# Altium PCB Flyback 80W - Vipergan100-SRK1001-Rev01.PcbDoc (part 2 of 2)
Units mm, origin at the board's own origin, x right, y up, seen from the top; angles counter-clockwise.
Board outline 121.92 x 39.12 mm, 2 copper layers (Top Layer, Bottom Layer), stack 1.58 mm thick; 100 components, 56 nets, 249 pads, 157 vias.
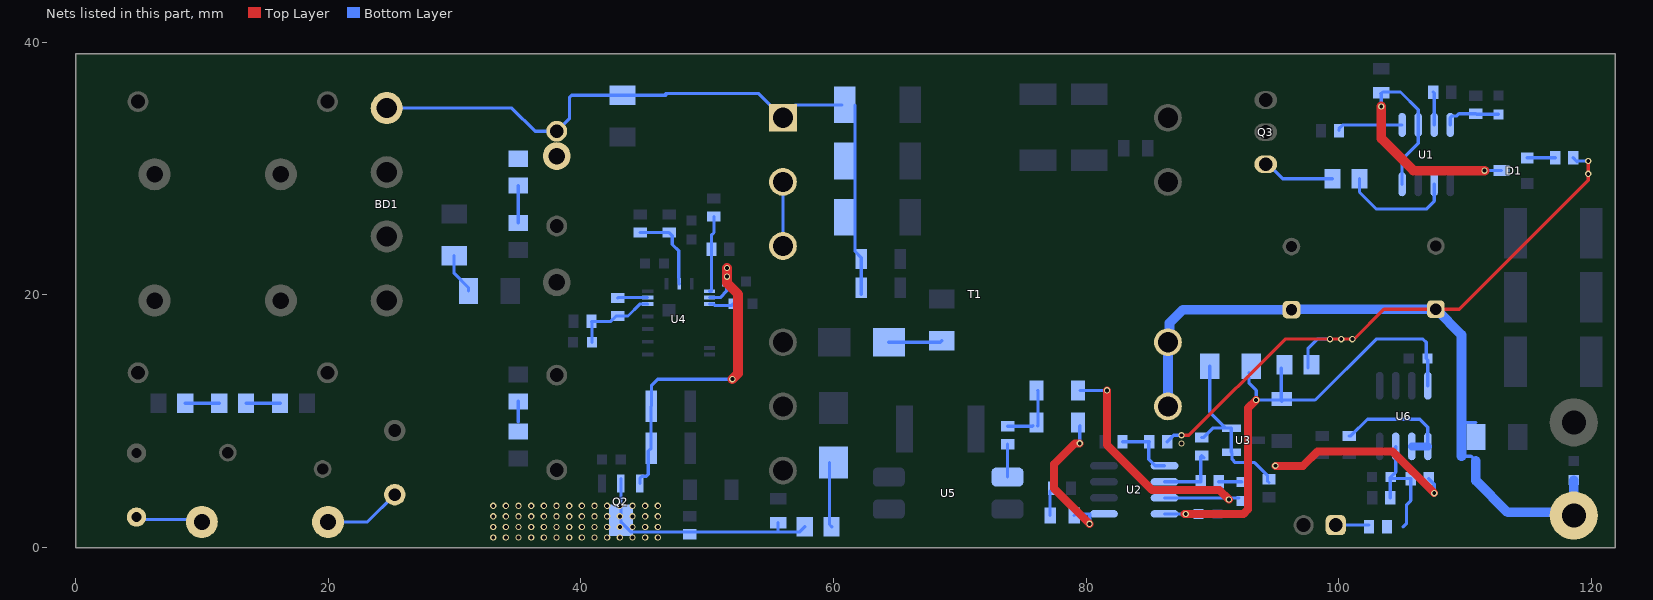
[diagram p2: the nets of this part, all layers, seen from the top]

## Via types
v1: diameter 0.508, hole 0.305, Top Layer to Bottom Layer, 157 vias

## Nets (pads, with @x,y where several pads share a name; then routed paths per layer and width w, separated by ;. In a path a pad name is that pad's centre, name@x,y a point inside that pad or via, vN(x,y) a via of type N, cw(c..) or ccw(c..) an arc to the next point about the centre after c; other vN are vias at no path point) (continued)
NetC12_2: C12.2 Q2.C R20.1 R24.2 | length 18.8
  Bottom Layer w0.254: Q2.C@43.18,2.18 43.18,2.052 44.003,1.229 55.626,1.229 ; Q2.C@43.18,2.561 Q2.C@43.18,5.461 ; C12.2@55.626,1.971 55.626,1.229 ; R20.1@57.734,1.651 57.312,1.229 55.626,1.229
  other v1: 35.073,0.8 36.075,0.8 37.078,0.8 38.08,0.8 39.083,0.8 40.085,0.8 41.088,0.8 42.091,0.8 43.093,0.8 44.096,0.8 45.098,0.8 46.101,0.8 33.067,0.801 34.07,0.801 33.067,1.634 34.07,1.634 35.073,1.633 36.075,1.633 37.078,1.633 38.08,1.633 39.083,1.633 40.085,1.633 41.088,1.633 42.091,1.633 43.093,1.633 44.096,1.633 45.098,1.633 46.101,1.633 33.067,2.468 34.07,2.468 35.073,2.467 36.075,2.467 37.078,2.467 38.08,2.467 39.083,2.467 40.085,2.467 41.088,2.467 42.091,2.467 43.093,2.467 44.096,2.467 45.098,2.467 46.101,2.467 33.067,3.303 34.07,3.303 35.073,3.302 36.075,3.302 37.078,3.302 38.08,3.302 39.083,3.302 40.085,3.302 41.088,3.3 42.091,3.3 43.093,3.3 44.096,3.3 45.098,3.3 46.101,3.3
NetC13_2: C13.2 R25.1 U1.8 | length 4.5
  Bottom Layer w0.254: U1.8@108.839,33.465 108.839,34.021 108.999,34.181 109.365,34.181 109.525,34.341 R25.1@110.871,34.341 110.91,34.302 C13.2@112.649,34.302
NetC19_1: C19.1 R30.1 | length 2.3
  Bottom Layer w0.254: C19.1@77.155,2.54 77.155,4.46 R30.1@77.394,4.699
NetC19_2: C19.2 D6.A U2.1 | length 12.1
  Top Layer w0.635: v1(79.502,8.255) 79.121,8.255 77.47,6.604 77.47,4.691 v1(80.28,1.882)
  Bottom Layer w0.254: C19.2@79.055,2.54 79.182,2.667 80.301,2.667 80.301,1.903 v1(80.28,1.882) ; v1(79.502,8.255) 79.502,9.628 D6.A@79.526,9.652
NetC20_2: C20.2 U4.13 | length 2
  Bottom Layer w0.254: U4.13@50.19,19.296 50.49,19.296 50.609,19.177 51.955,19.177 C20.2@52.082,19.304
NetC23_2: C23.2 R36.1 R40.2 U4.5 | length 6.7
  Bottom Layer w0.254: C23.2@40.882,16.256 40.882,17.868 R40.2@40.843,17.907 42.367,17.907 42.799,18.339 R36.1@42.926,18.339 43.739,18.339 44.678,19.278 45.272,19.278 U4.5@45.29,19.296
NetC24_1: C24.1 D7.A U2.7 | length 23.8
  Top Layer w0.635: v1(81.661,12.446) 81.661,8.128 85.217,4.572 90.551,4.572 v1(91.313,3.81)
  Bottom Layer w0.254: D7.A@79.526,12.446 v1(81.661,12.446) ; U2.7@86.22,3.937 C24.1@92.087,3.937
NetC24_2: C24.2 R35.1 | length 1.8
  Bottom Layer w0.254: R35.1@90.5,5.207 92.317,5.207 C24.2@92.329,5.195
NetC27_2: C27.2 R29.2 R46.2 R47.1 U6.3 | length 10
  Bottom Layer w0.254: R29.2@104.089,3.937 104.089,5.549 C27.2@104.128,5.588 ; U6.3@104.521,8.014 104.521,5.981 C27.2@104.128,5.588 ; 105.105,1.651 105.385,1.93 105.385,3.391 105.715,3.721 R46.2@105.715,5.461 104.255,5.461 C27.2@104.128,5.588
NetD1_A: D1.A R19.2 | length 2.2
  Bottom Layer w0.254: D1.A@114.935,30.861 R19.2@117.145,30.861
NetD3_K: D3.K R17.2 | length 4.2
  Bottom Layer w0.254: D3.K@64.389,16.256 68.453,16.256 R17.2@68.58,16.383
NetD5_K: D5.K R20.2 | length 5.2
  Bottom Layer w0.254: D5.K@59.69,6.731 59.69,1.829 R20.2@59.868,1.651
NetD6_K: D6.K D7.K R42.2 | length 4.8
  Bottom Layer w0.254: R42.2@73.787,9.601 75.744,9.601 D6.K@75.795,9.652 ; D6.K@76.176,9.652 76.2,9.676 76.2,12.422 D7.K@76.176,12.446
NetF1_1: F1.1 N.1 | length 5.3
  Bottom Layer w0.254: F1.1@4.826,2.413 5.016,2.222 9.81,2.222 N.1@10,2.032
NetL_1: L.1 NTC1.1 | length 6.2
  Bottom Layer w0.254: L.1@20,2.032 23.114,2.032 NTC1.1@25.273,4.191
NetP1_1: P1.1 R47.2 | length 2.6
  Bottom Layer w0.254: P1.1@99.77,1.778 R47.2@102.413,1.778
NetQ3_G: Q3.G R26.1 | length 5.8
  Bottom Layer w0.254: Q3.G@94.234,30.353 94.434,30.353 95.577,29.21 R26.1@99.517,29.21
NetR1_2: R1.2 R2.1 | length 2.7
  Bottom Layer w0.254: R2.1@13.513,11.43 R1.2@16.205,11.43
NetR2_2: R2.2 R7.1 | length 2.7
  Bottom Layer w0.254: R7.1@8.687,11.43 R2.2@11.379,11.43
NetR3_2: R3.2 R4.2 | length 2.9
  Bottom Layer w0.254: R4.2@35.052,25.705 R3.2@35.052,28.651
NetR5_2: R5.2 R6.1 | length 3.3
  Bottom Layer w0.254: R5.2@29.972,23.114 29.972,21.717 31.115,20.574 R6.1@31.115,20.32
NetR8_2: R8.2 R9.1 | length 1.6
  Bottom Layer w0.254: 35.052,9.957 R8.2@35.052,11.582
NetR18_2: R18.2 U1.5 | length 5.3
  Bottom Layer w0.254: R18.2@100.025,33.02 100.025,33.147 100.343,33.465 U1.5@105.029,33.465
NetR21_1: R21.1 U1.7 | length 2.6
  Bottom Layer w0.254: R21.1@107.493,36.068 107.569,35.992 U1.7@107.569,33.465
NetR26_2: R26.2 U1.2 | length 9.1
  Bottom Layer w0.254: R26.2@101.651,29.21 101.651,28.143 102.997,26.797 106.934,26.797 107.569,27.432 U1.2@107.569,28.765
NetR35_2: R35.2 R41.1 U2.6 | length 5.2
  Bottom Layer w0.254: U2.6@86.22,5.207 R35.2@89.078,5.207 89.078,7.214 R41.1@89.154,7.29 R41.1@89.332,7.112
NetR36_2: R36.2 U4.6 | length 2.4
  Bottom Layer w0.254: R36.2@42.926,19.761 42.961,19.796 U4.6@45.29,19.796
NetR39_2: R39.2 R43.1 U2.5 | length 5
  Bottom Layer w0.254: R43.1@82.88,8.382 R39.2@85.014,8.382 84.963,8.331 84.963,6.983 85.469,6.477 U2.5@86.22,6.477
NetR42_1: R42.1 U5.1 | length 2.6
  Bottom Layer w0.254: U5.1@73.787,5.588 R42.1@73.787,8.179
NetR48_2: R48.2 U6.1 U6.2 | length 9.8
  Bottom Layer w0.254: R48.2@100.838,8.839 100.965,8.839 102.286,10.16 106.426,10.16 107.061,9.525 U6.1@107.061,8.014
  Bottom Layer w0.635: U6.2@105.791,8.014 U6.1@107.061,8.014
NetT1_2: T1.2 T1.3 | length 5.1
  Bottom Layer w0.254: T1.3@56.007,23.876 T1.2@56.007,28.956
TB: R37.2 R44.1 U4.9 | length 6.7
  Bottom Layer w0.254: R37.2@44.704,24.943 R44.1@46.99,24.943 47.248,24.685 47.248,23.999 47.752,23.495 47.752,21.354 47.767,21.339 47.767,20.919 U4.9@47.79,20.896
Vcc_SRK: C14.2 D1.K U1.4 U1.6 | length 24
  Top Layer w0.762: v1(103.378,34.925) 103.378,32.385 105.918,29.845 v1(111.55,29.845)
  Bottom Layer w0.254: v1(103.378,34.925) 103.378,35.875 103.312,35.941 103.378,35.941 103.505,36.068 104.902,36.068 106.299,34.671 106.299,32.004 105.029,30.734 U1.4@105.029,28.765 ; v1@111.76,29.845 D1.K@112.903,29.845
Vdc_Bus: BD1.1 C3.2 C9.2 C10.2 pad.2@38.1,31 R3.1 R11.1 R12.1 R13.1 R22.1 T1.1 | length 55.4
  Bottom Layer w0.254: BD1.1@24.638,34.798 34.544,34.798 36.382,32.96 C3.2@38.1,32.96 39.116,33.976 39.116,35.665 39.265,35.814 46.736,35.814 ; 46.736,35.941 54.102,35.941 T1.1@56.007,34.036 57.023,35.052 R13.1@60.693,35.052 ; R13.1@61.709,35.052 61.709,30.607 61.709,26.162 61.709,23.451 62.204,22.956 62.204,22.606 C9.2@62.204,20.066
Vdd_Viper: C17.2 C18.2 C21.2 Q2.E U4.12 | length 27.3
  Top Layer w0.762: v1(51.574,22.135) 51.574,20.943 52.451,20.066 52.451,13.781 v1(52.005,13.335)
  Bottom Layer w0.254: Q2.E@44.68,5.08 44.68,5.48 44.853,5.653 45.19,5.653 45.339,5.802 45.339,7.646 C17.2@45.567,7.874 C18.2@45.567,11.176 45.593,11.202 45.593,12.827 46.101,13.335 v1(52.005,13.335) ; U4.12@50.19,19.796 51.038,19.796 51.562,20.32 51.562,21.07 C21.2@51.574,21.082 v1(51.574,21.457) ; 51.574,21.832 v1(51.574,22.135)
Vout: C6.1 C7.1 C8.2 R19.1 R23.1 R33.1 R39.1 T1.8 T1.9 V+.1 | length 104.7
  Top Layer w0.254: v1@87.503,8.89 v1(87.561,8.89) 88.138,8.89 95.758,16.51 v1(99.314,16.51) v1(100.203,16.51) v1(101.092,16.51) 101.219,16.51 103.585,18.876 C7.1@107.696,18.876 109.554,18.876 119.761,29.083 v1(119.761,29.591) v1(119.761,30.607)
  Bottom Layer w0.254: R39.1@86.436,8.382 86.944,8.89 v1@87.503,8.89 ; R33.1@97.587,14.224 97.587,15.799 98.298,16.51 v1(99.314,16.51) ; 109.728,7.239 110.49,7.239 110.871,6.858 ; 109.728,9.906 110.871,9.906 ; R19.1@118.567,30.861 118.872,30.556 118.923,30.607 v1(119.761,30.607)
  Bottom Layer w0.762: T1.8@86.487,11.176 T1.9@86.487,16.256 86.614,16.383 86.614,17.78 87.67,18.836 C6.1@96.266,18.836 96.286,18.856 107.676,18.856 C7.1@107.696,18.876 109.728,16.844 109.728,9.906 109.728,7.239 ; 110.871,6.858 110.871,5.299 113.376,2.794 118.364,2.794 V+.1@118.618,2.54 C8.2@118.618,5.346
  other v1: 87.561,8.243
Vref: R32.2 R34.2 R41.2 R46.1 U3.1 U3.2 | length 30.2
  Top Layer w0.635: v1(94.996,6.477) 97.189,6.477 98.332,7.62 104.267,7.62 v1(107.569,4.318)
  Bottom Layer w0.254: R41.2@89.154,8.712 89.281,8.712 90.028,9.459 U3.2@91.056,9.459 ; R32.2@89.789,14.351 89.789,10.726 U3.2@91.056,9.459 ; R34.2@94.488,5.156 94.361,5.283 94.361,5.715 93.345,6.731 91.821,6.731 91.567,6.985 91.567,7.498 U3.1@91.506,7.559 U3.2@91.506,9.459 U3.2@91.056,9.459 ; R46.1@107.137,5.461 107.569,5.029 v1(107.569,4.318)
Vreg: C25.2 C28.2 DZ3.K R32.1 R33.2 U2.8 U6.8 | length 40.9
  Top Layer w0.635: v1@87.8,2.661 92.465,2.661 92.837,3.033 92.837,11.049 v1(93.472,11.684)
  Bottom Layer w0.254: U2.8@86.22,2.667 C25.2@88.912,2.667 ; R32.1@92.913,13.843 92.913,13.005 93.472,12.446 v1(93.472,11.684) 95.401,11.684 DZ3.K@95.453,11.632 ; R33.2@95.453,14.224 DZ3.K@95.453,11.632 ; U6.8@107.061,12.814 107.061,14.847 106.922,14.986 106.934,14.998 106.934,16.256 106.68,16.51 102.966,16.51 98.14,11.684 95.607,11.684 95.504,11.581 DZ3.K@95.453,11.632
  other v1: 87.9,2.661
ZCD: R38.2 R45.1 U4.11 | length 6.1
  Bottom Layer w0.254: U4.11@50.19,20.296 50.32,20.296 50.343,20.319 50.343,22.606 50.343,24.74 50.546,24.943 R38.2@50.546,26.213
pads on no net: D1.NC U6.5 U6.6 U6.7

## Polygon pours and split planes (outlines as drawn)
GND-Out on Bottom Layer "NONET_L02_P-001" (solid, pour order 234): 97.663,0.381 98.298,1.016 98.298,2.604 98.869,3.175 105.054,3.175 106.162,4.298 106.162,8.372 106.162,15.855 90.922,15.855 88.392,13.325 88.392,9.525 87.239,8.372 84.308,8.372 83.312,9.368 83.312,16.002 82.55,16.764 78.613,16.764 77.079,15.23 77.079,9.886 75.428,8.235 75.428,7.473 75.428,7.346 75.428,5.822 75.306,5.7 73.782,5.7 72.136,4.054 72.136,3.038 72.136,1.143 72.898,0.381
GND-prim on Bottom Layer "NONET_L02_P-001" (solid, pour order 192): 53.911,18.287 53.658,18.034 49.631,18.034 48.26,16.663 48.26,14.859 46.228,14.859 39.751,8.382 39.751,6.096 38.735,5.08 31.369,5.08 28.194,8.255 28.194,13.335 23.622,17.907 23.114,17.907 22.733,18.288 22.733,20.701 23.114,21.082 25.527,21.082 26.416,20.193 26.416,18.669 30.734,14.351 30.734,9.271 32.258,7.747 37.084,7.747 37.084,7.239 37.465,7.239 37.465,9.398 44.704,16.637 44.704,18.288 44.958,18.542 47.616,18.542 47.871,18.288
NetC12_2 on Bottom Layer "NONET_L02_P-001" (solid, pour order 290): 32.258,3.556 32.639,3.937 39.751,3.937 40.005,3.683 42.291,3.683 42.672,4.064 42.672,5.969 43.561,5.969 43.561,4.318 44.069,3.81 46.482,3.81 46.863,3.429 46.863,1.905 47.244,1.524 50.292,1.524 51.689,2.921 58.293,2.921 58.547,2.667 58.547,0.635 58.293,0.381 32.639,0.381 32.258,0.762
NetC5_2 on Bottom Layer "NONET_L02_P-001" (solid, pour order 289): 49.53,1.905 47.752,1.905 47.498,2.159 47.498,3.683 46.736,4.445 46.736,5.461 46.863,5.588 49.403,5.588 49.657,5.334 49.657,2.032
GND-prim on Bottom Layer "NONET_L02_P-001" (solid, pour order 240): 38.1,16.024 37.915,16.209 37.915,18.865 38.1,19.05 38.862,19.05 43.376,23.564 43.376,31.242 51.689,31.242 52.959,29.972 52.959,22.733 54.229,21.463 54.229,18.605 53.658,18.034 45.667,18.034 42.238,14.605 39.497,14.605 39.001,15.101 38.1,16.002
NetC9_1 on Bottom Layer "NONET_L02_P-001" (solid, pour order 183): 69.596,37.719 69.596,24.384 70.104,23.876 70.104,19.304 69.723,18.923 65.151,18.923 64.516,19.558 64.516,23.876 64.897,24.257 64.897,37.719 65.405,38.227 69.088,38.227
Drain_Viper on Bottom Layer "NONET_L02_P-001" (solid, pour order 170): 56.896,14.986 57.531,14.351 61.087,14.351 61.468,14.732 61.468,17.78 55.626,17.78 53.848,16.002 49.53,16.002 49.53,14.986
NetD5_K on Bottom Layer "NONET_L02_P-001" (solid, pour order 272): 58.42,8.382 61.595,8.382 61.849,8.128 61.849,0.635 61.595,0.381 59.182,0.381 59.055,0.508 59.055,3.302 58.166,4.191 58.166,8.128
NetC2_1 on Bottom Layer "NONET_L02_P-001" (solid, pour order 288): 22.352,9.398 21.717,9.398 20.447,8.128 19.812,7.493 18.796,7.493 18.542,7.239 18.542,5.461 18.796,5.207 21.844,5.207 24.511,7.874 25.908,7.874 26.416,8.382 26.416,11.43 23.241,14.605 22.352,14.605 20.193,16.764 20.193,18.034 17.018,21.209 15.113,21.209 14.478,20.574 14.478,18.415 17.653,15.24 17.653,10.033 17.907,9.779 22.352,9.779
NetC2_2 on Bottom Layer "NONET_L02_P-001" (solid, pour order 287): 12.573,6.35 13.081,6.858 13.081,8.89 12.573,9.398 8.001,9.398 7.239,10.16 7.239,17.907 7.874,18.542 7.874,20.828 7.366,21.336 4.445,21.336 3.556,20.447 3.556,6.858 4.064,6.35
NetF1_1 on Bottom Layer "NONET_L02_P-001" (solid, pour order 285): 3.683,0.381 3.302,0.762 3.302,3.175 3.683,3.556 11.176,3.556 11.557,3.175 11.557,0.762 11.176,0.381
NetL_1 on Bottom Layer "NONET_L02_P-001" (solid, pour order 284): 24.257,0.381 26.416,2.54 26.416,4.826 25.908,5.334 24.511,5.334 22.987,3.81 18.923,3.81 18.415,3.302 18.415,0.889 18.923,0.381
GND-Sec on Bottom Layer "NONET_L02_P-001" (solid, pour order 283): 74.168,34.671 74.549,34.29 81.28,34.29 83.439,36.449 88.392,36.449 89.154,35.687 90.043,36.576 91.821,36.576 91.821,38.1 91.313,38.608 74.549,38.608 74.168,38.227
NetC11_1 on Bottom Layer "NONET_L02_P-001" (solid, pour order 282): 83.566,27.813 82.931,27.178 74.676,27.178 74.168,27.686 74.168,32.131 81.28,32.131 82.042,32.893 83.312,32.893 83.566,32.639
Drain_SR on Bottom Layer "NONET_L02_P-001" (solid, pour order 281): 87.249,27.051 87.884,27.686 87.884,35.179 87.503,35.56 84.836,35.56 84.455,35.179 84.455,27.559 84.963,27.051
HV on Bottom Layer "NONET_L02_P-001" (solid, pour order 279): 42.037,33.528 44.831,33.528 44.958,33.401 44.958,31.623 43.18,29.845 43.18,24.257 43.561,23.876 46.355,23.876 47.117,23.114 47.112,20.313 47.092,20.294 46.488,20.294 46.488,21.711 46.045,22.154 46.045,23.075 45.625,23.495 43.053,23.495 41.402,25.146 41.402,32.893
NetC5_2 on Bottom Layer "NONET_L02_P-001" (solid, pour order 278): 42.037,4.064 42.164,4.191 42.164,8.382 42.037,8.509 41.148,8.509 41.021,8.382 41.021,4.191 41.148,4.064
GND-prim on Bottom Layer "NONET_L02_P-001" (solid, pour order 277): 42.545,6.35 43.942,6.35 44.069,6.477 44.069,10.033 43.942,10.16 42.545,10.16 42.418,10.033 42.418,6.477
Vdd_Viper on Bottom Layer "NONET_L02_P-001" (solid, pour order 276): 49.276,13.843 52.324,13.843 52.451,13.716 52.451,13.081 52.324,12.954 49.281,12.959 47.118,12.955 46.228,12.065 46.228,4.826 45.72,4.318 44.323,4.318 44.323,12.192 45.974,13.843
GND-prim on Bottom Layer "NONET_L02_P-001" (solid, pour order 275): 63.881,12.319 63.817,12.255 63.627,12.065 63.627,7.874 64.516,6.985 66.294,6.985 66.294,4.064 66.167,3.937 62.992,3.937 62.865,3.81 62.865,0.635 63.119,0.381 65.786,0.381 67.056,1.651 67.056,11.811 66.548,12.319
GND-prim on Bottom Layer "NONET_L02_P-001" (solid, pour order 271): 48.006,5.969 50.546,5.969 51.308,5.207 51.308,3.429 56.642,3.429 57.277,4.064 57.277,6.731 56.642,7.366 52.324,7.366 51.689,8.001 51.689,12.065 51.054,12.7 48.133,12.7 47.625,12.192 47.625,6.35
Vout on Bottom Layer "NONET_L02_P-001" (solid, pour order 229): 108.458,6.223 108.458,4.953 113.03,0.381 114.3,0.381 120.523,0.381 121.539,1.397 121.539,4.699 120.396,5.842 117.729,5.842 116.586,4.699 113.792,4.699 111.76,6.731 111.76,10.668 111.506,10.922 111.506,18.542 109.22,20.828 87.503,20.828 84.836,18.161 84.836,10.668 85.725,9.779 87.503,9.779 88.011,10.287 88.011,16.129 89.535,17.653 107.442,17.653 108.077,17.018 108.077,6.604
Vout on Bottom Layer "NONET_L02_P-001" (solid, pour order 270): 118.364,32.004 118.11,31.75 118.11,29.337 118.364,29.083 120.142,29.083 120.396,29.337 120.396,31.75 120.142,32.004
NetC27_2 on Bottom Layer "NONET_L02_P-001" (solid, pour order 269): 103.637,3.17 103.632,3.164 103.632,2.794 103.378,2.54 103.378,0.635 103.632,0.381 106.045,0.381 106.489,0.825 106.489,3.874 106.172,4.191 106.172,6.223 106.045,6.35 105.283,6.35 105.029,6.604 105.029,9.144 104.902,9.271 104.267,9.271 104.14,9.144 104.14,6.731 103.632,6.223 103.632,3.175
NetP1_1 on Bottom Layer "NONET_L02_P-001" (solid, pour order 268): 102.87,2.921 103.124,2.667 103.124,0.635 102.87,0.381 99.06,0.381 98.806,0.635 98.806,2.667 99.06,2.921
GND-Sec on Bottom Layer "NONET_L02_P-001" (solid, pour order 265): 115.189,33.017 112.9,30.734 110.998,30.734 110.744,30.48 110.744,27.559 110.617,27.432 106.172,27.432 105.918,27.686 105.918,30.607 107.315,32.004 109.22,32.004 110.363,33.147 113.538,33.147 113.792,33.401 113.792,35.179 113.665,35.306 108.458,35.306 108.331,35.433 108.331,37.465 108.204,37.592 106.299,37.592 105.918,37.211 99.06,37.211 96.52,34.671 93.599,34.671 93.599,38.1 94.107,38.608 113.665,38.608 115.189,37.084
NetR21_1 on Bottom Layer "NONET_L02_P-001" (solid, pour order 264): 107.823,32.385 107.95,32.512 107.95,37.211 107.823,37.338 106.553,37.338 106.426,37.211 106.426,35.433 107.188,34.671 107.188,32.512 107.315,32.385
NetC13_2 on Bottom Layer "NONET_L02_P-001" (solid, pour order 263): 109.22,32.385 110.236,33.401 113.411,33.401 113.538,33.528 113.538,34.798 113.411,34.925 108.839,34.925 108.458,34.544 108.458,32.512 108.585,32.385
NetR26_2 on Bottom Layer "NONET_L02_P-001" (solid, pour order 262): 101.219,30.607 100.965,30.353 100.965,27.178 101.6,26.543 107.569,26.543 107.95,26.924 107.95,29.591 107.823,29.718 107.315,29.718 107.188,29.591 107.188,27.559 106.807,27.178 104.013,27.178 103.124,28.067 103.124,30.226 102.743,30.607
Vcc_SRK on Bottom Layer "NONET_L02_P-001" (solid, pour order 261): 102.362,36.576 104.775,36.576 106.68,34.671 106.68,32.004 105.41,30.734 105.41,27.686 105.283,27.559 104.775,27.559 104.648,27.686 104.648,30.861 105.918,32.131 105.918,34.544 105.41,35.052 104.267,35.052 103.759,34.544 102.362,34.544 102.108,34.798 102.108,36.322
NetR18_2 on Bottom Layer "NONET_L02_P-001" (solid, pour order 260): 104.648,34.544 104.267,34.163 99.695,34.163 99.568,34.036 99.568,32.004 99.695,31.877 104.775,31.877 105.41,32.512 105.41,34.417 105.283,34.544
Drain_SR on Bottom Layer "NONET_L02_P-001" (solid, pour order 259): 96.901,33.655 97.409,34.163 98.933,34.163 99.06,34.036 99.06,32.004 98.933,31.877 97.282,31.877 97.028,32.131 93.345,32.131 93.218,32.258 93.218,33.528 93.345,33.655
Vcc_SRK on Bottom Layer "NONET_L02_P-001" (solid, pour order 258): 113.538,30.48 111.506,30.48 111.252,30.226 111.252,29.337 111.506,29.083 113.538,29.083 113.665,29.21 113.665,30.353
NetD1_A on Bottom Layer "NONET_L02_P-001" (solid, pour order 256): 114.808,32.131 117.348,32.131 117.602,31.877 117.602,29.337 117.348,29.083 116.586,29.083 115.443,30.226 114.427,30.226 114.3,30.353 114.3,31.623
Vref on Bottom Layer "NONET_L02_P-001" (solid, pour order 255): 106.807,6.35 107.95,6.35 108.077,6.223 108.077,4.191 107.823,3.937 106.934,3.937 106.68,4.191 106.68,6.223
NetR48_2 on Bottom Layer "NONET_L02_P-001" (solid, pour order 251): 100.203,8.382 101.727,8.382 101.854,8.509 101.854,9.144 102.489,9.779 104.902,9.779 105.41,9.271 105.41,6.985 105.664,6.731 107.315,6.731 107.569,6.985 107.569,9.906 106.934,10.541 100.203,10.541 100.076,10.414 100.076,8.509
NetR35_2 on Bottom Layer "NONET_L02_P-001" (solid, pour order 131): 88.011,5.588 88.265,5.842 88.265,7.62 88.392,7.747 89.789,7.747 89.916,7.62 89.916,6.604 89.535,6.223 89.535,4.445 88.138,4.445 87.757,4.826 85.09,4.826 84.963,4.953 84.963,5.461 85.09,5.588
Vref on Bottom Layer "NONET_L02_P-001" (solid, pour order 250): 90.551,15.875 90.678,15.748 90.678,10.922 91.44,10.16 92.202,10.16 92.329,10.033 92.329,9.144 92.202,9.017 92.202,8.128 92.329,8.001 92.329,7.239 93.091,7.239 93.472,6.858 95.377,6.858 95.631,6.604 95.631,5.207 95.377,4.953 93.599,4.953 93.345,5.207 93.345,5.969 93.091,6.223 90.805,6.223 90.297,6.731 90.297,7.874 89.916,8.255 88.392,8.255 88.138,8.509 88.138,9.652 88.392,9.906 88.392,15.748 88.519,15.875
GND-Sec on Bottom Layer "NONET_L02_P-001" (solid, pour order 244): 70.104,6.858 70.104,11.811 83.312,25.019 88.519,25.019 89.408,25.908 90.424,24.892 90.551,24.892 90.551,24.765 92.964,22.352 82.677,22.352 72.009,11.684 72.009,6.858
NetR5_2 on Bottom Layer "NONET_L02_P-001" (solid, pour order 249): 28.575,24.003 28.575,19.558 29.337,18.796 31.75,18.796 32.131,19.177 32.131,21.971 31.496,22.606 31.496,24.003
NetBD1_3 on Bottom Layer "NONET_L02_P-001" (solid, pour order 248): 31.369,27.813 28.194,27.813 26.416,26.035 21.336,26.035 20.828,25.527 5.207,25.527 3.556,27.178 3.556,33.909 3.937,33.909 3.937,28.067 4.318,27.686 7.493,27.686 8.001,28.194 8.001,36.195 7.366,36.83 2.286,36.83 0.762,35.306 0.762,26.162 3.81,23.114 25.908,23.114 28.321,25.527 31.369,25.527
NetBD1_2 on Bottom Layer "NONET_L02_P-001" (solid, pour order 247): 21.463,31.369 21.082,31.75 21.082,36.195 20.32,36.957 15.748,36.957 14.351,35.56 14.351,28.956 15.621,27.686 17.526,27.686 18.669,28.829 18.669,33.909 19.05,33.909 19.05,29.337 20.193,28.194 25.527,28.194 26.162,28.829 26.162,30.734 25.527,31.369
Vout on Bottom Layer "NONET_L02_P-001" (solid, pour order 245): 98.425,13.081 101.473,16.129 101.473,16.891 101.346,17.018 97.536,17.018 97.155,16.637 97.155,13.081
GND-Sec on Bottom Layer "NONET_L02_P-001" (solid, pour order 233): 97.663,8.382 99.568,8.382 99.568,9.525 99.822,9.779 99.822,10.414 99.695,10.541 98.044,10.541 97.663,10.16
In- on Bottom Layer "NONET_L02_P-001" (solid, pour order 230): 97.663,7.874 101.727,7.874 101.727,6.35 101.092,5.715 98.425,5.715 97.663,6.477
GND-Out on Bottom Layer "NONET_L02_P-001" (solid, pour order 226): 113.157,10.541 113.411,10.795 116.586,10.795 118.237,12.446 118.237,27.432 118.618,27.813 121.158,27.813 121.539,27.432 121.539,7.493 120.523,6.477 116.586,6.477 116.332,6.731 116.332,7.874 116.078,7.874 116.078,6.731 115.824,6.477 113.411,6.477 113.157,6.731
GND-Sec on Bottom Layer "NONET_L02_P-001" (solid, pour order 225): 115.443,11.684 115.189,11.43 112.268,11.43 112.014,11.684 112.014,20.32 109.982,22.352 91.821,22.352 89.154,25.019 89.154,37.211 90.551,38.608 94.361,38.608 95.504,37.465 95.504,35.052 95.123,34.671 92.329,34.671 91.694,34.036 91.694,26.543 92.71,25.527 110.109,25.527 112.268,27.686 114.808,27.686 115.443,27.051
NetQ3_G on Bottom Layer "NONET_L02_P-001" (solid, pour order 222): 100.203,28.067 99.949,27.813 94.488,27.813 92.837,29.464 92.837,30.734 93.345,31.242 94.996,31.242 95.631,30.607 99.949,30.607 100.203,30.353
Vreg on Bottom Layer "NONET_L02_P-001" (solid, pour order 216): 96.266,10.922 96.774,11.43 98.298,11.43 103.124,16.256 106.045,16.256 106.553,15.748 106.553,14.478 106.68,14.351 106.68,11.557 106.807,11.43 107.569,11.43 107.696,11.557 107.696,16.51 107.315,16.891 102.743,16.891 98.171,12.319 97.028,12.319 96.52,12.827 96.52,15.494 96.139,15.875 94.488,15.875 94.361,15.748 94.361,12.192 94.107,12.192 94.107,15.748 93.98,15.875 92.329,15.875 92.202,15.748 92.202,11.684 92.964,10.922
NetR8_2 on Bottom Layer "NONET_L02_P-001" (solid, pour order 191): 36.322,11.938 36.322,8.89 35.941,8.509 33.909,8.509 33.528,8.89 33.528,11.938 33.909,12.319 35.941,12.319
NetC23_2 on Bottom Layer "NONET_L02_P-001" (solid, pour order 206): 42.291,15.748 44.069,17.526 44.069,18.288 44.831,19.05 45.72,19.05 45.72,19.431 44.323,19.431 43.688,18.796 40.64,18.796 40.386,18.542 40.386,15.748
Aux on Bottom Layer "NONET_L02_P-001" (solid, pour order 205): 43.688,25.781 43.688,28.194 44.704,29.21 50.673,29.21 51.308,28.575 51.308,27.178 49.784,27.178 48.641,28.321 46.609,28.321 45.72,27.432 45.72,25.781
NetC20_2 on Bottom Layer "NONET_L02_P-001" (solid, pour order 204): 49.67,19.469 49.67,18.669 52.54,18.669 52.54,19.748 52.514,19.774 52.489,19.748 51.727,19.748 51.448,19.469
Vdd_Viper on Bottom Layer "NONET_L02_P-001" (solid, pour order 203): 49.708,19.634 49.708,19.964 50.775,19.964 51.079,20.269 51.079,21.514 50.927,21.666 50.927,22.301 51.079,22.454 51.994,22.454 52.172,22.276 52.172,21.539 51.968,21.336 51.968,20.371 51.232,19.634
ZCD on Bottom Layer "NONET_L02_P-001" (solid, pour order 202): 49.53,20.117 50.648,20.117 50.724,20.193 50.724,20.574 50.597,20.701 50.597,22.885 50.775,23.063 50.775,24.613 51.562,25.4 51.562,26.645 49.962,26.645 49.53,26.213
FB on Bottom Layer "NONET_L02_P-001" (solid, pour order 200): 48.26,24.892 48.26,23.876 48.387,23.749 48.387,20.574 48.514,20.447 49.149,20.447 49.276,20.574 49.276,24.892
NetR1_2 on Bottom Layer "NONET_L02_P-001" (solid, pour order 199): 16.764,10.16 12.827,10.16 12.7,10.287 12.7,12.573 12.827,12.7 16.764,12.7 16.891,12.573 16.891,10.287
NetR2_2 on Bottom Layer "NONET_L02_P-001" (solid, pour order 198): 8.128,12.7 8.001,12.573 8.001,10.287 8.128,10.16 11.938,10.16 12.065,10.287 12.065,12.573 11.938,12.7
TB on Bottom Layer "NONET_L02_P-001" (solid, pour order 196): 43.688,25.4 43.688,24.13 46.736,24.13 47.498,23.368 47.498,20.447 48.006,20.447 48.006,23.622 47.752,23.876 47.752,25.4
NetR36_2 on Bottom Layer "NONET_L02_P-001" (solid, pour order 194): 45.745,19.964 44.298,19.964 43.688,20.574 42.164,20.574 42.037,20.447 42.037,19.304 42.164,19.177 43.561,19.177 44.018,19.634 45.745,19.634
NetC3_1 on Bottom Layer "NONET_L02_P-001" (solid, pour order 189): 39.497,20.447 38.608,19.558 37.592,19.558 37.338,19.304 37.338,16.002 39.116,14.224 39.116,12.954 38.862,12.7 37.084,12.7 36.703,13.081 33.909,13.081 33.528,13.462 33.528,23.876 33.909,24.257 36.449,24.257 37.084,24.892 37.084,26.162 37.338,26.416 39.243,26.416 39.497,26.162
NetR3_2 on Bottom Layer "NONET_L02_P-001" (solid, pour order 188): 33.782,29.337 33.782,25.146 34.036,24.892 35.814,24.892 36.068,25.146 36.068,29.337
NetT1_2 on Bottom Layer "NONET_L02_P-001" (solid, pour order 184): 54.61,30.226 54.61,23.368 55.372,22.606 56.896,22.606 57.658,23.368 57.658,30.226 57.15,30.734 55.118,30.734
NetD3_K on Bottom Layer "NONET_L02_P-001" (solid, pour order 182): 62.992,14.732 63.373,14.351 69.469,14.351 69.85,14.732 70.358,15.24 70.358,17.018 69.977,17.399 67.183,17.399 66.802,17.78 62.992,17.78
Vdc_Bus on Bottom Layer "NONET_L02_P-001" (solid, pour order 181): 33.782,31.242 33.782,30.226 34.036,29.972 37.084,29.972 37.338,29.718 39.37,29.718 39.878,30.226 39.878,34.036 40.894,35.052 51.054,35.052 53.594,32.512 58.166,32.512 59.309,31.369 59.309,19.685 59.69,19.304 62.484,19.304 62.738,19.558 62.738,24.638 62.738,37.084 62.484,37.338 39.37,37.338 38.354,36.322 38.354,34.29 37.846,34.29 37.846,36.068 37.084,36.83 23.368,36.83 22.86,36.322 22.86,33.782 23.368,33.274 31.75,33.274
Aux on Bottom Layer "NONET_L02_P-001" (solid, pour order 176): 54.991,12.573 57.277,12.573 57.658,12.954 61.595,12.954 61.849,12.7 61.849,9.906 61.595,9.652 57.531,9.652 57.277,9.906 55.118,9.906 54.61,10.414 54.61,12.192
FB on Bottom Layer "NONET_L02_P-001" (solid, pour order 119): 63.119,4.699 62.738,5.08 62.738,6.858 63.119,7.239 63.754,7.239 64.389,6.604 65.659,6.604 65.913,6.35 65.913,4.953 65.659,4.699
In- on Bottom Layer "NONET_L02_P-001" (solid, pour order 151): 96.139,3.429 96.266,3.556 96.266,4.445 96.139,4.572 93.853,4.572 93.726,4.445 93.726,3.556 93.853,3.429
NetC24_1 on Bottom Layer "NONET_L02_P-001" (solid, pour order 148): 82.042,13.462 82.169,13.335 82.169,11.684 82.042,11.557 78.867,11.557 78.74,11.684 78.74,13.335 78.867,13.462
NetC19_2 on Bottom Layer "NONET_L02_P-001" (solid, pour order 147): 80.137,10.541 80.264,10.414 80.264,8.001 80.137,7.874 78.867,7.874 78.74,8.001 78.74,10.414 78.867,10.541
NetC24_1 on Bottom Layer "NONET_L02_P-001" (solid, pour order 145): 92.71,4.191 87.376,4.191 87.249,4.318 85.09,4.318 84.963,4.191 84.963,3.683 85.09,3.556 91.059,3.556 91.694,2.921 92.71,2.921 92.837,3.048 92.837,4.064
Vreg on Bottom Layer "NONET_L02_P-001" (solid, pour order 144): 85.09,2.159 84.963,2.286 84.963,3.048 85.09,3.175 89.281,3.175 89.408,3.048 89.408,2.286 89.281,2.159
In- on Bottom Layer "NONET_L02_P-001" (solid, pour order 143): 80.391,3.556 80.264,3.683 78.41,3.683 78.41,6.198 78.562,6.35 79.375,6.35 79.502,6.223 79.502,4.572 79.756,4.318 82.423,4.318 82.55,4.191 82.55,3.683 82.423,3.556
NetC19_2 on Bottom Layer "NONET_L02_P-001" (solid, pour order 141): 78.486,3.302 79.756,3.302 80.01,3.048 82.55,3.048 82.677,2.921 82.677,1.524 82.55,1.397 78.486,1.397
NetC19_1 on Bottom Layer "NONET_L02_P-001" (solid, pour order 140): 77.851,3.556 77.724,3.429 77.724,1.651 77.597,1.524 76.581,1.524 76.454,1.651 76.454,3.175 76.835,3.556 76.835,5.715 76.962,5.842 77.724,5.842 77.851,5.715
NetR42_1 on Bottom Layer "NONET_L02_P-001" (solid, pour order 139): 74.422,8.636 74.549,8.509 74.549,6.985 75.184,6.35 75.184,4.699 75.057,4.572 72.517,4.572 72.39,4.699 72.39,6.35 73.025,6.985 73.025,8.509 73.152,8.636
NetD6_K on Bottom Layer "NONET_L02_P-001" (solid, pour order 138): 76.835,13.589 76.835,8.89 76.708,8.763 75.057,8.763 74.676,9.144 73.152,9.144 73.025,9.271 73.025,10.287 73.152,10.414 74.422,11.684 74.422,12.954 75.311,13.843 76.581,13.843
Vout on Bottom Layer "NONET_L02_P-001" (solid, pour order 135): 85.979,9.144 86.106,9.271 87.757,9.271 87.884,9.144 87.884,7.62 87.757,7.493 86.106,7.493 85.979,7.62
NetC24_2 on Bottom Layer "NONET_L02_P-001" (solid, pour order 132): 90.043,5.969 92.71,5.969 92.837,5.842 92.837,4.699 92.71,4.572 90.043,4.572
NetR39_2 on Bottom Layer "NONET_L02_P-001" (solid, pour order 130): 82.55,9.271 85.344,9.271 85.471,9.144 85.471,6.985 85.598,6.858 87.249,6.858 87.376,6.731 87.376,6.223 87.249,6.096 85.09,6.096 84.709,6.477 84.709,7.493 84.455,7.747 82.55,7.747 82.423,7.874 82.423,9.144
NetC12_2 on Top Layer "NONET_L02_P-001" (solid, pour order 291): 38.735,3.937 40.259,5.461 44.577,5.461 46.101,3.937 51.054,3.937 51.689,3.302 51.689,1.016 51.054,0.381 32.639,0.381 32.258,0.762 32.258,3.556 32.639,3.937
GND-prim on Top Layer "NONET_L02_P-001" (solid, pour order 280): 48.26,27.051 48.26,24.765 47.879,24.384 47.879,22.098 48.641,21.336 48.641,19.177 49.276,18.542 49.276,15.367 48.387,14.478 48.387,11.557 49.784,10.16 51.689,10.16 52.197,9.652 52.197,6.35 56.515,2.032 65.659,2.032 65.913,1.778 65.913,1.016 65.659,0.762 55.626,0.762 49.784,6.604 49.784,7.112 48.768,8.128 47.117,8.128 42.926,8.128 42.418,8.636 42.418,12.319 40.005,14.732 40.005,19.685 43.053,22.733 43.053,29.337 44.958,31.242 51.689,31.242 53.213,29.718 53.213,22.479 53.721,21.971 53.721,21.082 53.594,20.955 52.705,20.955 52.324,21.336 52.324,22.352 51.308,23.368 51.308,28.067 49.911,29.464 48.006,29.464 47.625,29.083 47.625,28.448 48.26,27.813
GND-Sec on Top Layer "NONET_L02_P-001" (solid, pour order 266): 110.998,30.861 110.998,35.56 109.601,36.957 104.648,36.957 104.394,37.211 104.394,38.354 104.648,38.608 113.665,38.608 115.189,37.084 115.189,30.353 112.268,27.432 109.728,27.432 109.601,27.559 109.601,28.829 109.982,29.21 112.268,29.21 112.522,29.464 112.522,30.226 112.268,30.48 111.379,30.48
Vout on Top Layer "NONET_L02_P-001" (solid, pour order 246): 120.142,28.702 120.142,31.242 120.015,31.369 119.253,31.369 119.126,31.242 119.126,28.956 110.109,19.939 103.886,19.939 100.965,17.018 95.631,17.018 88.011,9.398 87.376,9.398 87.122,9.144 87.122,8.075 87.297,7.899 87.824,7.899 95.885,15.961 101.94,15.961 103.886,17.907 109.347,17.907
GND-Out on Top Layer "NONET_L02_P-001" (solid, pour order 236): 109.824,0.35 115.793,6.319 118.968,6.319 120.873,8.224 120.873,13.685 119.095,15.463 95.473,15.463 87.624,7.614 85.923,7.614 83.662,9.875 83.662,15.463 82.392,16.733 78.836,16.733 76.423,14.32 71.978,9.875 71.978,1.112 72.74,0.35
GND-Sec on Top Layer "NONET_L02_P-001" (solid, pour order 232): 103.886,10.668 105.664,12.446 114.808,12.446 115.062,12.192 115.062,11.811 114.808,11.557 106.299,11.557 104.521,9.779 98.044,9.779 97.917,9.906 97.917,10.541 98.044,10.668
Drain_SR on Top Layer "NONET_L02_P-001" (solid, pour order 223): 92.837,32.131 89.662,28.956 89.662,27.432 89.281,27.051 84.709,27.051 83.693,28.067 83.693,34.417 84.709,35.433 90.995,35.433 92.773,33.655 94.996,33.655 95.25,33.401 95.25,32.385 94.996,32.131

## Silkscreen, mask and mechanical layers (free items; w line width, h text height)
Top Overlay:
  drawing of 3 lines, arcs and shapes, not listed
  text "life.augmented" at 113.665,33.274 h0.76
  text "Flyback: ViperGan100 / Sync. Rect: SRK1001 / Rev: April 2024" at 120.65,12.827 h0.8 r90
Bottom Overlay:
  drawing of 13 lines, arcs and shapes, not listed
  text "WARNING" at 18.342,2.105 h1
Board Outline:
  lines w0.508: 0,0 0,39.116 121.92,39.116 121.92,0 0,0
  lines w0.762: 54.102,30.226 54.102,23.114 55.118,22.098
  lines w1.016: 21.971,32.004 21.971,36.83 ; 58.674,18.542 63.246,18.542 ; 69.088,1.143 69.088,12.319 74.422,17.653 ; 72.136,26.67 72.136,37.084
Info:
  drawing of 199 lines, arcs and shapes, not listed
  text "PCB Technical Specification" at 127.254,79.502 h1.52
  text "- Laminate Type: FR4 / - Total Size (mm): 39.12 x 121.92 / - Thickeness: 1.60mm (+/- 10%) / - Number of Layers: 2 / - Finishing HASL Lead Free / - Finished Copper Thickness: 2.756 mil (2 oz) / - Solder Mask: Top and Bottom (Green) / - Silkscreen Top: Yes, White / - Silkscreen Bottom: Yes, White / - Drills Tolerances (if not specified): +/- 0.08mm. / - Vias not covered" at 127,45.72 h1.52
  text "Layer" at 129.389,36.398 h1.52
  text "Name" at 139.8,36.398 h1.52
  text "Material" at 163.416,36.398 h1.52
  text "Thickness" at 185.254,36.398 h1.52
  text "Constant" at 201.76,36.398 h1.52
  text "Board Layer Stack" at 216.234,36.398 h1.52
  text "Top Overlay" at 139.8,33.35 h1.52
  text "Top Solder" at 139.8,30.302 h1.52
  text "Solder Resist" at 163.416,30.302 h1.52
  text "0.010mm" at 185.254,30.302 h1.52
  text "3.5" at 201.76,30.302 h1.52
  text "1" at 129.389,27.254 h1.52
  text "Top Layer" at 139.8,27.254 h1.52
  text "Copper" at 163.416,27.254 h1.52
  text "0.070mm" at 185.254,27.254 h1.52
  text "Dielectric 1" at 139.8,24.206 h1.52
  text "FR-4" at 163.416,24.206 h1.52
  text "1.440mm" at 185.254,24.206 h1.52
  text "4.8" at 201.76,24.206 h1.52
  text "2" at 129.389,21.158 h1.52
  text "Bottom Layer" at 139.8,21.158 h1.52
  text "Copper" at 163.416,21.158 h1.52
  text "0.070mm" at 185.254,21.158 h1.52
  text "Bottom Solder" at 139.8,18.11 h1.52
  text "Solder Resist" at 163.416,18.11 h1.52
  text "0.010mm" at 185.254,18.11 h1.52
  text "3.5" at 201.76,18.11 h1.52
  text "Bottom Overlay" at 139.8,15.062 h1.52
  text "Total board thickness:" at 129.389,12.014 h1.52
  text "1.600mm" at 185.254,12.014 h1.52
Drill Drawing:
  circle w0.254: c-0.07,57.87 r0.847
  lines w0.254: -0.917,49.826 -0.493,49.826 -0.493,49.403 0.353,49.403 0.353,49.826 0.777,49.826 0.777,50.673 0.353,50.673 0.353,51.096 -0.493,51.096 -0.493,50.673 -0.917,50.673 -0.917,49.826 ; -0.917,53.213 0.777,53.213 0.777,54.906 -0.917,54.906 -0.917,53.213 ; -0.917,60.833 -0.07,61.256 0.777,60.833 0.353,61.68 0.777,62.526 -0.07,62.103 -0.917,62.526 -0.493,61.68 -0.917,60.833 ; -0.917,65.49 -0.07,64.643 0.777,65.49 -0.07,66.336 -0.917,65.49 ; -0.917,68.453 -0.917,68.876 -0.493,69.3 -0.917,69.723 -0.917,70.146 -0.493,70.146 -0.07,69.723 0.353,70.146 0.777,70.146 0.777,69.723 0.353,69.3 0.777,68.876 0.777,68.453 0.353,68.453 -0.07,68.876 -0.493,68.453 -0.917,68.453 ; -0.917,73.956 0.777,73.956 -0.07,72.263 -0.917,73.956 ; -0.917,76.073 0.777,76.073 0.777,77.766 -0.917,77.766 -0.917,76.073 ; -0.917,80.306 -0.493,80.306 -0.07,79.883 0.353,80.306 0.777,80.306 0.353,80.73 0.777,81.153 0.353,81.153 -0.07,81.576 -0.493,81.153 -0.917,81.153 -0.493,80.73 -0.917,80.306 ; -0.578,61.172 -0.07,61.426 0.438,61.172 0.184,61.68 0.438,62.188 -0.07,61.934 -0.578,62.188 -0.324,61.68 -0.578,61.172 ; -0.578,76.412 0.438,76.412 0.438,77.428 -0.578,77.428 -0.578,76.412
  lines w0.381: -2.435,48.26 121.281,48.26 ; -2.435,82.55 121.281,82.55 ; 11.557,44.45 11.557,86.36 ; 26.793,44.45 26.793,86.36 ; 54.725,44.45 54.725,86.36 ; 67.574,44.45 67.574,86.36 ; 86.213,44.45 86.213,86.36 ; 101.195,44.45 101.195,86.36 ; -2.435,44.45 121.281,44.45 121.281,86.36 -2.435,86.36 -2.435,44.45
  text "Symbol" at -0.149,83.693 h1.83
  text "Count" at 12.7,83.693 h1.83
  text "Hole Size" at 27.936,83.693 h1.83
  text "Plated" at 55.868,83.693 h1.83
  text "Hole Type" at 68.717,83.693 h1.83
  text "Via/Pad" at 87.356,83.693 h1.83
  text "Pad Shape" at 102.338,83.693 h1.83
  text "157" at 12.7,79.883 h1.52
  text "12.01mil (0.305mm)" at 27.936,79.883 h1.52
  text "PTH" at 55.868,79.883 h1.52
  text "Round" at 68.717,79.883 h1.52
  text "Via" at 87.356,79.883 h1.52
  text "Rounded" at 102.338,79.883 h1.52
  text "2" at 12.7,76.073 h1.52
  text "31.50mil (0.800mm)" at 27.936,76.073 h1.52
  text "PTH" at 55.868,76.073 h1.52
  text "Round" at 68.717,76.073 h1.52
  text "Pad" at 87.356,76.073 h1.52
  text "Rounded" at 102.338,76.073 h1.52
  text "6" at 12.7,72.263 h1.52
  text "35.43mil (0.900mm)" at 27.936,72.263 h1.52
  text "PTH" at 55.868,72.263 h1.52
  text "Round" at 68.717,72.263 h1.52
  text "Pad" at 87.356,72.263 h1.52
  text "(Mixed)" at 102.338,72.263 h1.52
  text "2" at 12.7,68.453 h1.52
  text "39.37mil (1.000mm)" at 27.936,68.453 h1.52
  text "PTH" at 55.868,68.453 h1.52
  text "Round" at 68.717,68.453 h1.52
  text "Pad" at 87.356,68.453 h1.52
  text "Rounded" at 102.338,68.453 h1.52
  text "13" at 12.7,64.643 h1.52
  text "43.31mil (1.100mm)" at 27.936,64.643 h1.52
  text "PTH" at 55.868,64.643 h1.52
  text "Round" at 68.717,64.643 h1.52
  text "Pad" at 87.356,64.643 h1.52
  text "(Mixed)" at 102.338,64.643 h1.52
  text "2" at 12.7,60.833 h1.52
  text "50.00mil (1.270mm)" at 27.936,60.833 h1.52
  text "PTH" at 55.868,60.833 h1.52
  text "Round" at 68.717,60.833 h1.52
  text "Pad" at 87.356,60.833 h1.52
  text "Rounded" at 102.338,60.833 h1.52
  text "6" at 12.7,57.023 h1.52
  text "51.18mil (1.300mm)" at 27.936,57.023 h1.52
  text "PTH" at 55.868,57.023 h1.52
  text "Round" at 68.717,57.023 h1.52
  text "Pad" at 87.356,57.023 h1.52
  text "Rounded" at 102.338,57.023 h1.52
  text "14" at 12.7,53.213 h1.52
  text "62.99mil (1.600mm)" at 27.936,53.213 h1.52
  text "PTH" at 55.868,53.213 h1.52
  text "Round" at 68.717,53.213 h1.52
  text "Pad" at 87.356,53.213 h1.52
  text "(Mixed)" at 102.338,53.213 h1.52
  text "2" at 12.7,49.403 h1.52
  text "75.00mil (1.905mm)" at 27.936,49.403 h1.52
  text "PTH" at 55.868,49.403 h1.52
  text "Round" at 68.717,49.403 h1.52
  text "Pad" at 87.356,49.403 h1.52
  text "Rounded" at 102.338,49.403 h1.52
  text "204 Total" at 12.7,45.593 h1.52

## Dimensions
121.92,0 to 0,0 on Info
0,0 to 0,39.116 on Info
